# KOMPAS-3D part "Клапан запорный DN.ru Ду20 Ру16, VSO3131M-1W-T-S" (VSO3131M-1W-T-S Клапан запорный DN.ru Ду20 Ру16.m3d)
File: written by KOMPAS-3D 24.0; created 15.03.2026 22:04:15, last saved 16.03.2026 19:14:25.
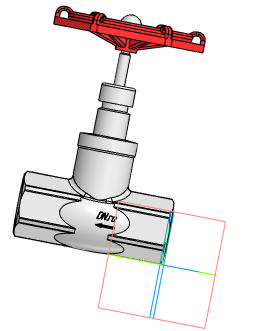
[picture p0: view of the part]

Document properties: Автор: artiomk228874@gmail.com; Полное имя файла: VSO3131M-1W-T-S Клапан запорный DN.ru Ду20 Ру16.cdw

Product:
- Body: Тело 1  | qty 1
    Масса: 0.280197
- Part/product: Клапан запорный DN.ru Ду20 Ру16  | designation VSO3131M-1W-T-S
    Масса: 0.38
    Раздел спецификации: Прочие изделия
    Форматы листов документа: A2
    Примечание: D100-03670
    additional columns: 94d3474e-3e6e-4ddd-ad0b-ef51eb5e31da; VSO3131M-1W-T-S; Сталь 10 ГОСТ 1050-2013; artiomk228874@gmail.com; c; Шероховатость не задана; Да

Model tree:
1. Операция без истории:1

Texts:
  VSO3131M-1W-T-S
